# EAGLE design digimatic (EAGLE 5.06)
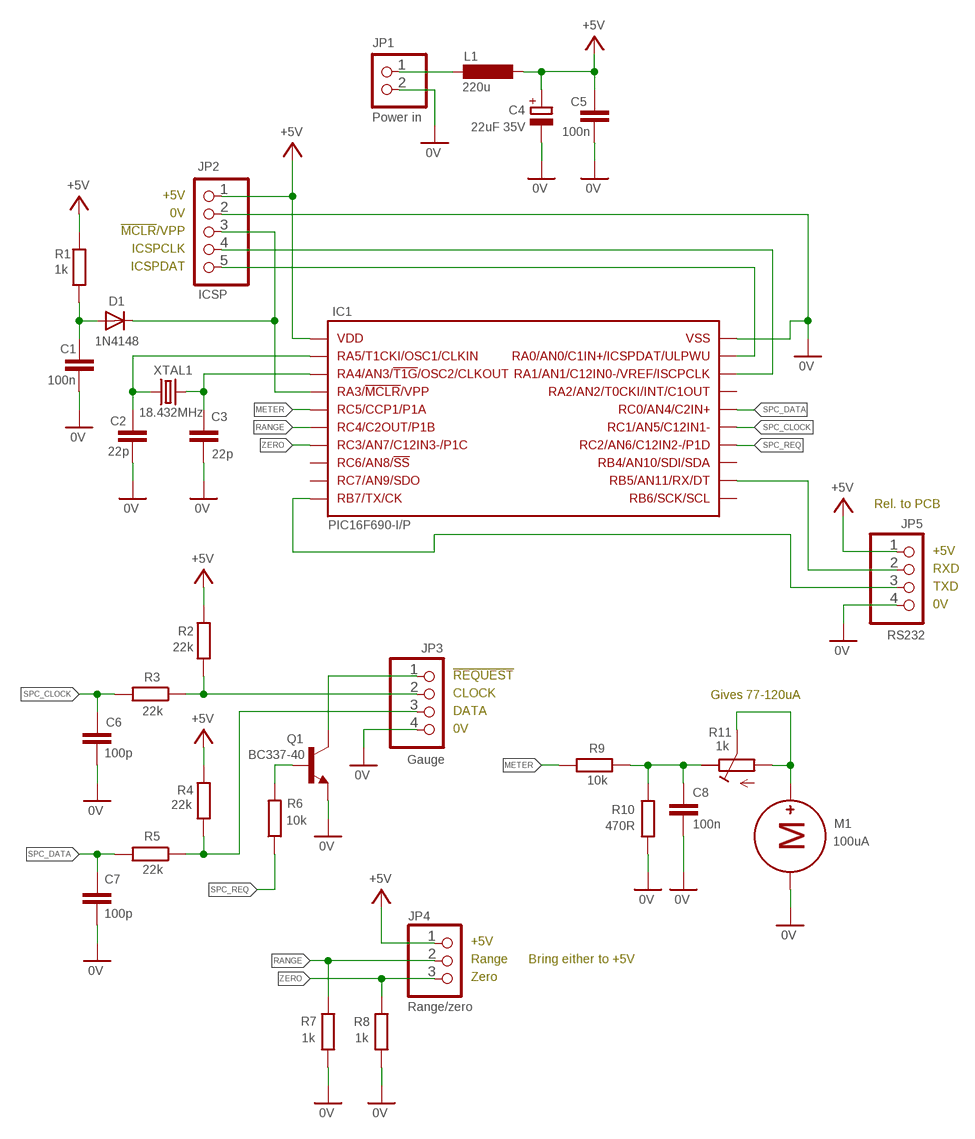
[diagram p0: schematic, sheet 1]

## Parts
C1  100n  C-EU050-024X044  [C050-024X044]
C2  22p  C-EU025-024X044  [C025-024X044]
C3  22p  C-EU025-024X044  [C025-024X044]
C4  22uF 35V  CPOL-EUE2.5-7  [E2,5-7]
C5  100n  C-EU050-024X044  [C050-024X044]
C6  100p  C-EU025-024X044  [C025-024X044]
C7  100p  C-EU025-024X044  [C025-024X044]
C8  100n  C-EU050-024X044  [C050-024X044]
D1  1N4148  1N4148DO35-7  [DO35-7]
IC1  PIC16F690-I/P  [SOCKET-20]
JP1  Power in  PINHD-1X2  [1X02]
JP2  ICSP  PINHD-1X5  [1X05]
JP3  Gauge  PINHD-1X4  [1X04]
JP4  Range/zero  PINHD-1X3  [1X03]
JP5  RS232  PINHD-1X4  [1X04]
L1  220u  L-EU0309V  [0309V]
M1  100uA  METERNODIM  [RAPID-NODIM]
Q1  BC337-40  BC337-40-A  [TO92-EBC]
R1  1k  R-EU_0207/7  [0207/7]
R2  22k  R-EU_0207/7  [0207/7]
R3  22k  R-EU_0207/7  [0207/7]
R4  22k  R-EU_0207/7  [0207/7]
R5  22k  R-EU_0207/7  [0207/7]
R6  10k  R-EU_0207/7  [0207/7]
R7  1k  R-EU_0207/2V  [0207/2V]
R8  1k  R-EU_0207/2V  [0207/2V]
R9  10k  R-EU_0207/2V  [0207/2V]
R10  470R  R-EU_0207/2V  [0207/2V]
R11  1k  RTRIM-3  [RTRIM3]
XTAL1  18.432MHz  CRYSTALHC49U-V  [HC49U-V]

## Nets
0V: C1.2 C2.2 C3.2 C4.- C5.2 C6.2 C7.2 C8.2 IC1.20 JP1.2 JP2.2 JP3.4 JP5.4 M1.- Q1.E R7.1 R8.1 R10.2
+5V: C4.+ C5.1 IC1.1 JP2.1 JP4.1 JP5.1 L1.1 R1.2 R2.2 R4.2
METER: IC1.5 R9.1
N$1: JP1.1 L1.2
N$2: JP3.1 Q1.C
N$3: IC1.12 JP5.2
N$5: C2.1 IC1.2 XTAL1.1
N$6: C3.1 IC1.3 XTAL1.2
N$7: C1.1 D1.A R1.1
N$8: D1.C IC1.4 JP2.3
N$9: IC1.18 JP2.4
N$10: IC1.19 JP2.5
N$11: M1.+ R11.P$1(ACW) R11.P$2(COM)
N$12: C8.1 R9.2 R10.1 R11.P$3(CW)
N$13: Q1.B R6.2
N$15: JP3.2 R2.1 R3.1
N$18: JP3.3 R4.1 R5.1
RANGE: IC1.6 JP4.2 R7.2
RB7: IC1.10 JP5.3
SPC_CLOCK: C6.1 IC1.15 R3.2
SPC_DATA: C7.1 IC1.16 R5.2
SPC_REQ: IC1.14 R6.1
ZERO: IC1.7 JP4.3 R8.2
Unconnected: IC1.8 IC1.9 IC1.11 IC1.13 IC1.17

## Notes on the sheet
- +5V
- 0V
- !MCLR!/VPP
- ICSPCLK
- ICSPDAT
- Rel. to PCB
- +5V
- RXD
- TXD
- 0V
- !REQUEST
- CLOCK | Gives 77-120uA
- DATA
- 0V
- +5V
- Range | Bring either to +5V
- Zero

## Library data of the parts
C1-C3 C5-C8 = rcl:C-EU: CAPACITOR, European symbol
C4 = rcl:CPOL-EU: POLARIZED CAPACITOR, European symbol
D1 = diode:1N4148: DIODE
IC1 = lindsay-micro:PIC16F690
JP1 = pinhead:PINHD-1X2: PIN HEADER
JP2 = pinhead:PINHD-1X5: PIN HEADER
JP3 JP5 = pinhead:PINHD-1X4: PIN HEADER
JP4 = pinhead:PINHD-1X3: PIN HEADER
L1 = rcl:L-EU: INDUCTOR, European symbol
M1 = lindsay-meter:METER
Q1 = transistor-npn:BC337*: NPN Transistor
R1-R10 = rcl:R-EU_: RESISTOR, European symbol
R11 = lindsay-rcl:RTRIM: Pin numbering - the pin nearer the winder seems to usually be #1
XTAL1 = crystal:CRYSTAL: CRYSTAL

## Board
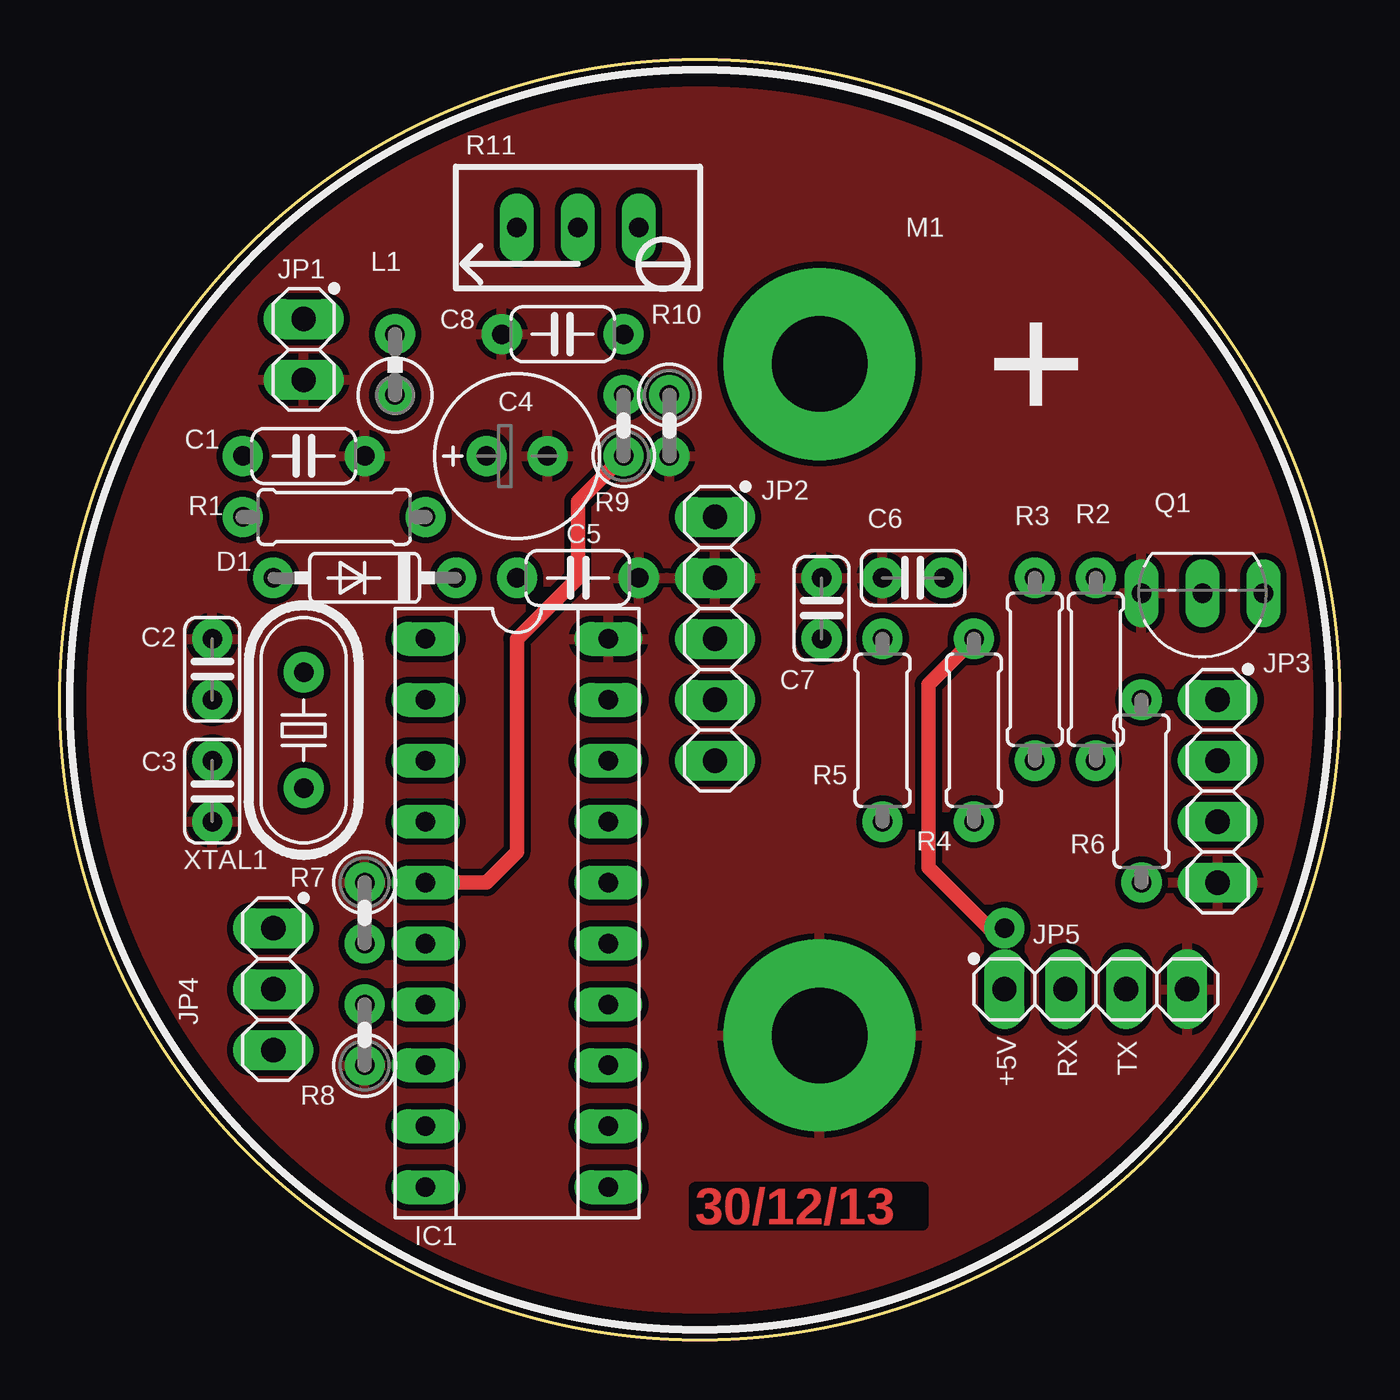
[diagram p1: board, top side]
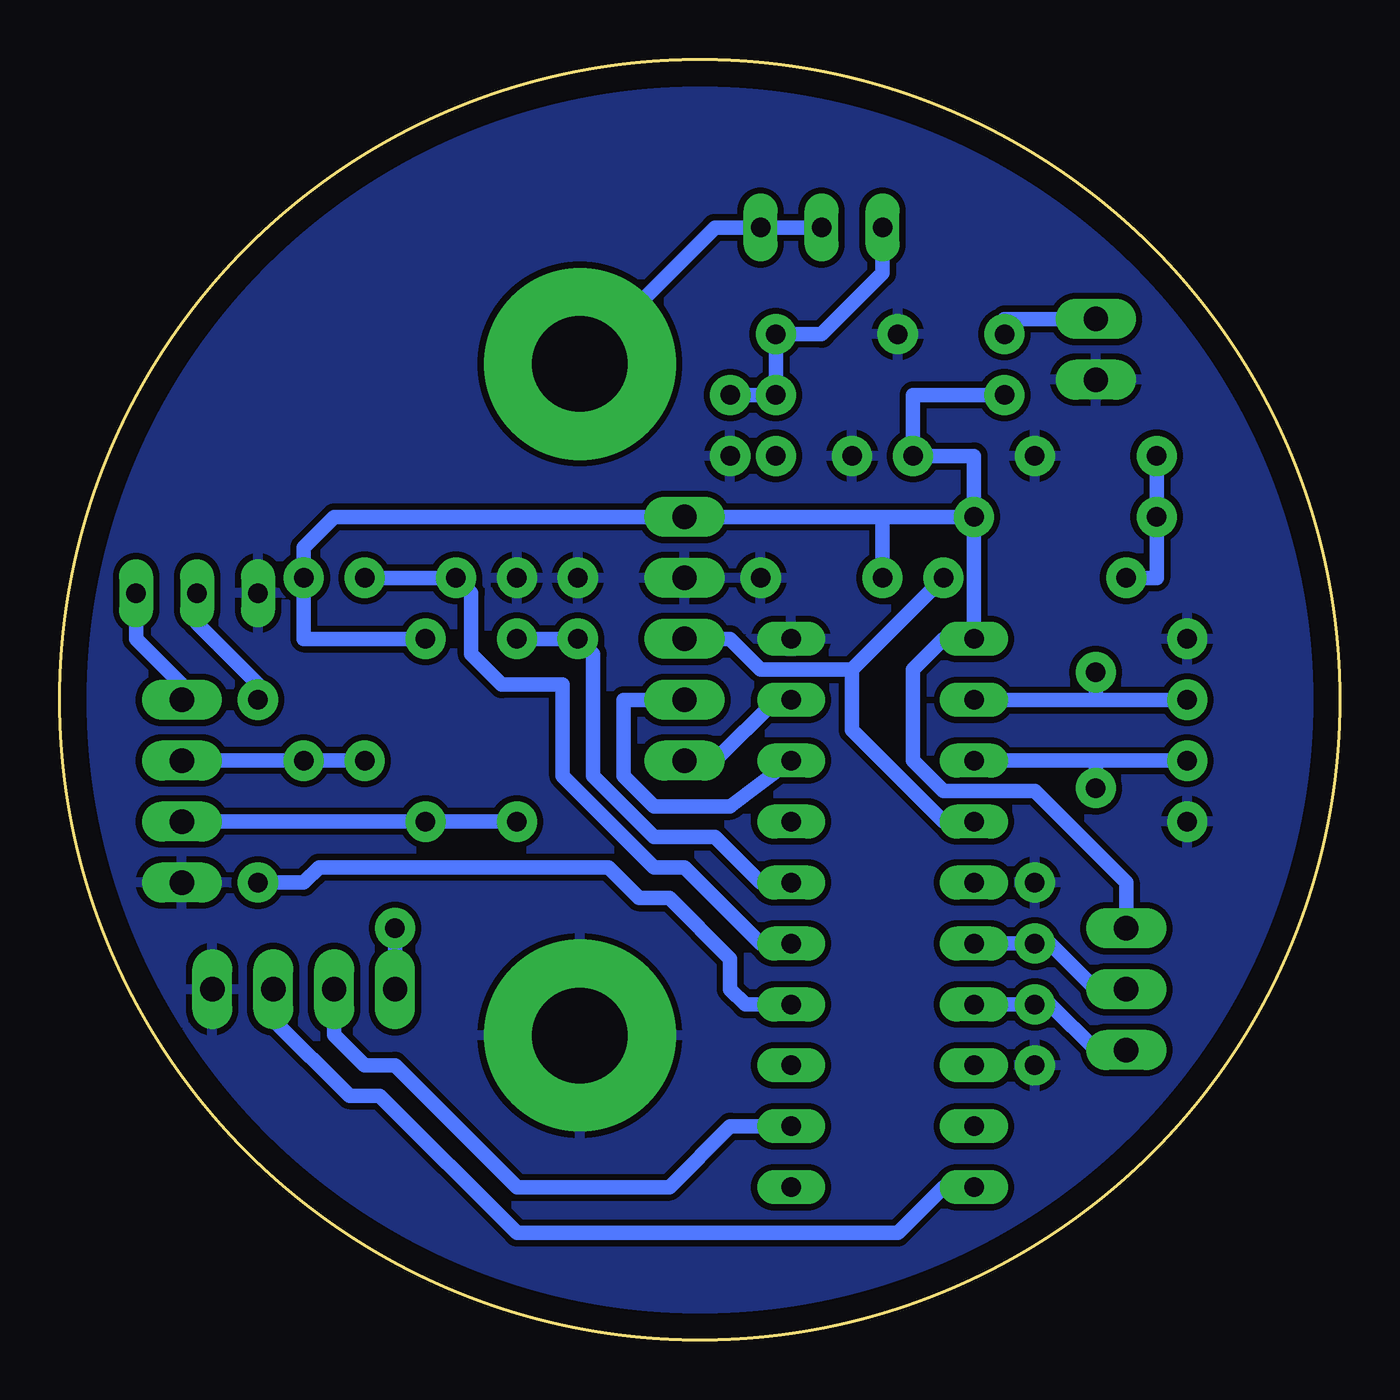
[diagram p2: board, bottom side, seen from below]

Size 53.34 x 53.34 mm. Coordinates in mm from the lower left corner, seen from the top.
Outline: circle at 26.67,26.67 radius 26.67
Copper layers (1*16): Top 0.035mm / dielectric 1.5mm / Bottom 0.035mm
Design rules "default": minimum track width 10mil, minimum drill 24mil, track to track 8mil, track to pad 8mil, pad to pad 8mil, via to via 8mil, smd to smd 8mil, copper to edge 40mil, drill to drill 8mil, minimum pad ring 10mil, minimum via ring 8mil, stop-mask expansion 4mil, vias tented up to drill 0mil, thermal gap 10mil

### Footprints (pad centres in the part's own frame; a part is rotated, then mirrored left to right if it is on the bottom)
C050-024X044 = drill 0.813 pad 1.676 round: 1 -2.54,0; 2 2.54,0
C025-024X044 = drill 0.813 pad 1.676 round: 1 -1.27,0; 2 1.27,0
E2,5-7 = drill 0.813 pad 1.676 round: + -1.27,0; - 1.27,0
DO35-7 = drill 0.813 pad 1.676 round: A 3.81,0; C -3.81,0
SOCKET-20 = drill 0.813 pad 1.422 long: 1 -11.43,-3.81; 2 -8.89,-3.81; 3 -6.35,-3.81; 4 -3.81,-3.81; 5 -1.27,-3.81; 6 1.27,-3.81; 7 3.81,-3.81; 8 6.35,-3.81; 9 8.89,-3.81; 10 11.43,-3.81; 11 11.43,3.81; 12 8.89,3.81; 13 6.35,3.81; 14 3.81,3.81; 15 1.27,3.81; 16 -1.27,3.81; 17 -3.81,3.81; 18 -6.35,3.81; 19 -8.89,3.81; 20 -11.43,3.81
1X02 = drill 1.016 pad 1.676 long: 1 -1.27,0; 2 1.27,0
1X05 = drill 1.016 pad 1.676 long: 1 -5.08,0; 2 -2.54,0; 3 0,0; 4 2.54,0; 5 5.08,0
1X04 = drill 1.016 pad 1.676 long: 1 -3.81,0; 2 -1.27,0; 3 1.27,0; 4 3.81,0
1X03 = drill 1.016 pad 1.676 long: 1 -2.54,0; 2 0,0; 3 2.54,0
0309V = drill 0.813 pad 1.676 round: 1 -1.27,0; 2 1.27,0
RAPID-NODIM = drill 3.988 pad 8.001 round: + -14,5; - 14,5
TO92-EBC = drill 0.813 pad 1.422 long: B 0,0; C -2.54,0; E 2.54,0
0207/7 = drill 0.813 pad 1.676 round: 1 -3.81,0; 2 3.81,0
0207/2V = drill 0.813 pad 1.676 round: 1 -1.27,0; 2 1.27,0
RTRIM3 = drill 0.813 pad 1.422 long: P$1 2.54,0; P$2 0,0; P$3 -2.54,0
HC49U-V = drill 0.813 pad 1.676 round: 1 -2.413,0; 2 2.413,0

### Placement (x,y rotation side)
C1  10.16,36.83 0 top
C2  6.35,27.94 90 top
C3  6.35,22.86 270 top
C4  19.05,36.83 0 top
C5  21.59,31.75 0 top
C6  35.56,31.75 180 top
C7  31.75,30.48 90 top
C8  20.96,41.91 180 top
D1  12.7,31.75 180 top
IC1  19.05,17.78 270 top
JP1  10.16,41.28 270 top
JP2  27.31,29.21 270 top
JP3  48.26,22.86 270 top
JP4  8.89,14.61 270 top
JP5  43.18,14.61 0 top
L1  13.97,40.64 90 top
M1  26.67,26.67 270 top
Q1  47.62,31.12 180 top
R1  11.43,34.29 0 top
R2  43.18,27.94 90 top
R3  40.64,27.94 90 top
R4  38.1,25.4 90 top
R5  34.29,25.4 90 top
R6  45.09,22.86 90 top
R7  12.7,17.78 270 top
R8  12.7,12.7 90 top
R9  23.5,38.1 90 top
R10  25.4,38.1 270 top
R11  21.59,46.36 0 top
XTAL1  10.16,25.4 270 top

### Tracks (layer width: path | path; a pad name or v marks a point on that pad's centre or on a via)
0V
  pour Bottom (isolate 0.254): 0,53.34 53.34,53.34 53.34,0 0,0
  pour Top (isolate 0.254): 0,53.34 53.34,53.34 53.34,0 0,0
+5V  (via drill 0.81 pad 1.68)
  Top 0.61: v39.37,17.15 38.73,17.15 36.2,19.69 36.2,27.31 R4.2
  Bottom 0.61: R1.2 IC1.1 16.51,29.21 17.78,27.94 17.78,24.13 16.51,22.86 12.7,22.86 8.89,19.05 JP4.1 | L1.1 17.78,39.37 C4.+ 15.24,36.83 R1.2 | R1.2 19.05,34.29 | 19.05,34.29 JP2.1 41.91,34.29 43.18,33.02 R2.2 43.18,29.21 R4.2 | 19.05,34.29 C5.1 | v39.37,17.15 JP5.1
METER
  Top 0.61: IC1.5 17.78,19.05 19.05,20.32 19.05,29.21 21.59,31.75 21.59,34.93 22.23,35.56 R9.1
N$1
  Bottom 0.61: L1.2 13.97,42.55 JP1.1
N$2
  Bottom 0.61: JP3.1 48.26,27.31 50.17,29.21 Q1.C
N$3
  Bottom 0.61: IC1.12 25.4,8.89 27.94,6.35 34.29,6.35 39.37,11.43 40.64,11.43 41.91,12.7 JP5.2
N$5
  Bottom 0.61: 10.16,26.67 C2.1 | IC1.2 10.16,26.67 | 10.16,26.67 XTAL1.1
N$6
  Bottom 0.61: 10.16,24.13 C3.1 | IC1.3 10.16,24.13 | 10.16,24.13 XTAL1.2
N$7
  Bottom 0.61: C1.1 R1.1 7.62,31.75 D1.A
N$8
  Bottom 0.61: 20.32,27.94 20.32,25.4 16.51,21.59 IC1.4 | 20.32,27.94 D1.C | JP2.3 25.4,29.21 24.13,27.94 20.32,27.94
N$9
  Bottom 0.61: JP2.4 29.85,26.67 29.85,23.5 28.58,22.23 25.4,22.23 IC1.18
N$10
  Bottom 0.61: IC1.19 23.5,26.67 26.04,24.13 JP2.5
N$11
  Bottom 0.61: R11.P$2 R11.P$1 26.04,46.36 31.75,40.64 31.7,40.64 M1.+
N$12
  Bottom 0.61: R10.1 R9.2 C8.1 21.59,41.91 19.05,44.45 R11.P$3
N$13
  Bottom 0.61: R6.2 45.09,27.31 47.62,29.85 Q1.B
N$15
  Bottom 0.61: R3.1 R2.1 JP3.2
N$18
  Bottom 0.61: R5.1 R4.1 JP3.3
RANGE
  Bottom 0.61: IC1.6 R7.2 12.07,16.51 10.16,14.61 JP4.2
RB7
  Bottom 0.61: IC1.10 16.51,6.35 18.41,4.45 34.29,4.45 40.01,10.16 41.28,10.16 44.45,13.34 JP5.3
SPC_CLOCK
  Bottom 0.61: R3.2 C6.1 36.2,31.12 36.2,28.58 34.93,27.31 32.39,27.31 32.39,23.5 28.58,19.69 27.31,19.69 24.13,16.51 IC1.15
SPC_DATA
  Bottom 0.61: R5.2 C7.1 31.12,28.58 31.12,23.5 28.58,20.96 26.04,20.96 24.13,19.05 IC1.16
SPC_REQ
  Bottom 0.61: IC1.14 24.77,13.97 25.4,14.61 25.4,15.88 27.94,18.41 29.21,18.41 30.48,19.69 42.55,19.69 43.18,19.05 R6.1
ZERO
  Bottom 0.61: IC1.7 R8.2 12.07,13.97 10.16,12.07 JP4.3
(copper drawn outside any net)
  shapes: Top circle x1

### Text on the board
Top: 30/12/13
tPlace: +5V | RX | TX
